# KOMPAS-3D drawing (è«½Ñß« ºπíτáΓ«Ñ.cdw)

Referenced files: Колесо зубчатое.cdw
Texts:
  Колесо зубчатое
  Aleksey
  Noncommercial version
  max
  Js9
  Ra3.2
  Ra12.5
  Модуль
  Число зубьев
  Угол наклона
  Направление линии зуба
  Нормальный исходный
  контур
  Коэффициент смещения
  Степень точности
  Делительный диаметр
  левое
  ГОСТ
  Длина общей нормали
  Термообработка улучшение НВ 269..302
  Радиусы скруглений 2 мм мах
  Колесо
  зубчатое
  Сталь 45 ГОСТ 1050-88
Dimensions and other numbers on the sheet: 44; 0.008; 0.025; 0,4; 47,65; 12; 0.02; 236; 209; 151; 93; 1,5; 2 фаски; 18; 4 отв.; 2,5; 1; 15; 46; 1.5; 155; 13755-81; 0; 8 - В; 235; 85,45; 1:1; 27.06.06; 2; 3; 4; 5; 6; 7; 8; 9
